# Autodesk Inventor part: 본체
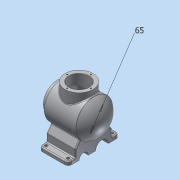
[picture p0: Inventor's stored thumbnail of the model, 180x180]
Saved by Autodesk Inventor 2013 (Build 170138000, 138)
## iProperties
Created: 2018-08
Part Number: 본체
Material: 알루미늄 6061
Document SubType Name: Modeling
Designer: dgall
Density: 2.71 g/cm^3
Mass: 1888.41 g
Surface Area: 1033.26 cm^2
Volume: 696.829 cm^3
Author: dgall
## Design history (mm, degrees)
sketch "스케치1"
  geometry: L1 (0, 0)-(130, 0); L2 (0, 0)-(0, 38); L3 (0, 38)-(12, 38); L4 (12, 38)-(12, 50); L5 (12, 50)-(101.394, 50); A1 r 58 centre (72, 0) between (130, 0) and (101.394, 50); 1 further point; 1 other entity
  constraints: 11 end point, 3 perpendicular, 2 point on circle, 1 centre point, 1 coincident, 1 horizontal, 1 point on line, 1 vertical, 2 other
  dimensions: "d1" = 76 diameter of L3 L1; "d12" = 12 distance between parallel lines of L4 L2; "d77" = 116 diameter of A1; "d80" = 100 diameter of L5 L1; "d109" = 60 distance from line of A1.centre L4
revolve "회전1" sketch "스케치1" stored, may be unused: angle "d11" = 90 deg
sketch "스케치3"
  geometry: L1 (0, 0)-(120, 0); L2 (0, 0)-(0, 27); L3 (0, -38)-(0, 38) reference; L4 (0, 0)-(0, 13.875); L5 (0, 27)-(20, 27); L6 (20, 27)-(20, 37); L7 (101.394, -50)-(101.394, 50) reference; L8 (12, -50)-(12, 50) reference; L9 (23, 40)-(98.533, 40); A1 r 3 centre (23, 37) between (23, 40) and (20, 37); A2 r 58 centre (72, 0) between (101.394, -50) and (101.394, 50) reference; A3 r 48 centre (72, 0) between (120, 0) and (98.533, 40); 1 further point
  constraints: 12 end point, 4 point on circle, 3 perpendicular, 2 centre point, 2 point on line, 2 tangent, 1 horizontal
  dimensions: "d19" = 8 distance between parallel lines of L6 L8; "d20" = 3 radius of A1; "d82" = 10 radial gap between concentric circles of A2 A3; "d83" = 54 diameter of L5 L1; "d100" = 80 diameter of L9 L1
  node "투영된 루프1"
fillet "모깎기1" dims "d25" = 3
fillet "모깎기2" dims "d26" = 3
sketch "스케치4" dims "d27" = 65
  geometry: L1 (0, 0)-(32.5, 0); 1 further point
  constraints: 2 end point, 2 horizontal alignment, 1 coincident, 1 horizontal, 2 other
hole "구멍1" sketch "스케치4" at (32.5, 0) diameter "d30" = 3.242; stored, may be unused: countersink angle "d34" = 82 deg, drill point angle "d36" = 118 deg; dims "d31" = 8, "d32" = 3.023, "d33" = 2, "d35" = 10
node "작업 평면1"
sketch "스케치5"
  geometry: L1 (100, 70)-(20, 70); L2 (20, 70)-(20, -70); L3 (20, -70)-(100, -70); L4 (100, -70)-(100, 70); L5 (12, -47)-(12, 47) reference; 1 further point
  constraints: 8 end point, 2 parallel, 1 horizontal, 1 perpendicular
  dimensions: "d74" = 8 distance between parallel lines of L5 L2; "d88" = 80 distance between parallel lines of L4 L2; "d89" = 140 distance between parallel lines of L3 L1; "d90" = 70 distance from line of point (0, 0) L1
extrude "돌출1" join sketch "스케치5" distance "d46" = 10; taper "d47" = 0 deg
node "작업 평면2"
sketch "스케치6"
  geometry: L1 (70, -72)-(-70, -72) reference; L2 (-50, -72)-(-50, -52); L3 (-50, -52)-(-36.821, -33.178); L4 (50, -72)-(50, -52); L5 (50, -52)-(36.821, -33.178); L6 (-70, -82)-(-70, -72) reference; L7 (70, -82)-(70, -72) reference; C1 r 50 at (0, 0) reference; A1 r 50 centre (0, 0) between (-37.078, -33.545) and (37.078, -33.545); 1 further point
  constraints: 8 end point, 4 point on line, 2 point on circle, 1 centre point, 1 coincident, 1 concentric, 1 horizontal alignment, 1 parallel, 1 perpendicular
  dimensions: "d49" = 35 deg angle of L6 L3; "d50" = 35 deg angle of L7 L5; "d51" = 20 distance between parallel lines of L7 L4; "d52" = 20 distance between parallel lines of L2 L6; "d53" = 20 distance from line of L1 L2.end
fillet "모깎기3" dims "d66" = 10
sketch "스케치8"
  geometry: C1 r 4 at (90, 60); C2 r 4 at (30, 60); A1 r 10 centre (30, 60) between (30, 70) and (20, 60) reference; A2 r 10 centre (90, 60) between (100, 60) and (90, 70) reference; 1 further point
  constraints: 2 centre point, 2 coincident
  dimensions: "d67" = 8 diameter of C1; "d69" = 8 diameter of C2
extrude "돌출4" cut sketch "스케치8" distance "d70" = 10; taper "d71" = 0 deg
revolve "회전3" stored, may be unused: angle "d84" = 90 deg
extrude "돌출6" join sketch "스케치6" stored distance "d93" = 80; taper "d94" = 0 deg
fillet "모깎기6" dims "d95" = 3
fillet "모깎기7" dims "d96" = 3
fillet "모깎기8" dims "d97" = 3
node "작업 평면3"
sketch "스케치9"
  geometry: C1 r 40 at (0, 0) reference; C2 r 27 at (0, 0) reference; C3 r 32.5 at (0, 0); 1 further point
  constraints: 1 centre point, 1 coincident, 1 other
  dimensions: "d101" = 65 diameter of C3
node "작업 평면4"
sketch "스케치10"
  geometry: C1 r 38 at (60, -0.23); 1 further point
  constraints: 1 centre point
  dimensions: "d104" = 76 diameter of C1; "d106" = 60 horizontal distance of C1.centre point (0, 0)
extrude "돌출7" join sketch "스케치10" stored distance "d107" = 0.5; taper "d108" = 0 deg
sketch "스케치11"
  geometry: C1 r 38 at (0, 0) reference; C2 r 27 at (0, 0); 1 further point
  constraints: 1 centre point, 1 coincident
  dimensions: "d110" = 54 diameter of C2
extrude "돌출8" cut sketch "스케치11" stored distance "d112" = 0.5; taper "d113" = 0 deg
chamfer "모따기2" distance "d114" = 1; stored, may be unused: second distance "d115" = 2, angle "d116" = 45 deg
sketch "스케치12" dims "d117" = 65
  geometry: C1 r 38 at (0, 0) reference; C2 r 28 at (0, 0) reference; 3 further points
  constraints: 2 vertical alignment, 1 coincident, 2 other
hole "구멍2" sketch "스케치12" at (0, 32.5) diameter "d119" = 3.242; stored, may be unused: countersink angle "d123" = 82 deg, drill point angle "d125" = 118 deg; dims "d120" = 8, "d121" = 3.023, "d122" = 2, "d124" = 10
fillet "모깎기9" dims "d129" = 3
chamfer "모따기3" distance "d130" = 1; stored, may be unused: second distance "d131" = 2, angle "d132" = 45 deg
fillet "모깎기10" dims "d133" = 2
fillet "모깎기11" dims "d134" = 3
sketch "스케치13"
  geometry: L1 (0, 0)-(0, 120) reference; C1 r 17.5 at (0, 82.5); C2 r 12.5 at (0, 32.5); A1 r 52.536 centre (-82, 60) between (-44.148, 23.569) and (-44.148, 96.431) reference
  constraints: 2 centre point, 2 point on line
  dimensions: "d135" = 25 diameter of C2; "d137" = 35 diameter of C1; "d138" = 27.5 vertical distance of A1.centre C2.centre; "d139" = 22.5 vertical distance of C1.centre A1.centre
extrude "돌출9" cut sketch "스케치13" stored distance "d140" = 0.5; taper "d141" = 0 deg
node "솔리드1"
mirror "대칭1"
pattern_circular "원형 패턴2" dims angle "d86" = 360 deg
pattern_circular "원형 패턴3" dims angle "d127" = 360 deg
other parameters: "d40" = -82, "d98" = 108, "d103" = 65
